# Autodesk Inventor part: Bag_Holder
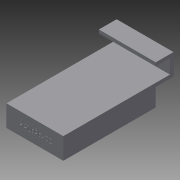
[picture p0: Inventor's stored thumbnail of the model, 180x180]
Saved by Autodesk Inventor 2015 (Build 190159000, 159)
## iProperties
Created: 2017-04
Part Number: Bag_Holder
Material: Generisch
Document SubType Name: Modeling
Designer: Andreas
Density: 1 g/cm^3
Appearance: Vorgabe
Author: Andreas
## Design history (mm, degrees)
sketch "Skizze1"
  geometry: L1 (0, 0)-(80, 0); L2 (80, 0)-(80, 130); L3 (80, 130)-(0, 130); L4 (0, 130)-(0, 0)
  constraints: 8 end point, 2 perpendicular, 1 horizontal
  dimensions: "d0" = 80 distance of L1.start L1.end; "d1" = 130 distance of L1.end L2.end; "d2" = 80 distance of L2.end L3.end
extrude "Extrusion1" new body sketch "Skizze1" distance "d3" = 30; taper "d4" = 0 deg
sketch "Skizze2"
  geometry: L1 (80, 0)-(0, 0) reference; L2 (0, 0)-(0, -30) reference; L3 (80, -30)-(0, -30) reference; L4 (80, 0)-(80, -30) reference; L5 (5, -25)-(5, -5); L6 (5, -5)-(75, -5); L7 (75, -5)-(75, -25); L8 (75, -25)-(5, -25); 1 further point
  constraints: 8 end point, 3 other
  dimensions: "d5" = 5 distance between parallel lines of L2 L5; "d77" = 20 distance of L5.start L5.end (derived); "d78" = 70 distance of L5.end L6.end (derived)
extrude "Extrusion2" cut sketch "Skizze2" distance "d6" = 125; taper "d7" = 0 deg
sketch "Skizze7"
  geometry: L1 (-59.744, 88.491)-(-60.39, 85.615); L2 (-62.939, 74.608)-(-63.588, 71.717); L3 (-52.046, 75.49)-(-55.468, 75.49); L4 (-55.468, 75.49)-(-53.397, 84.729); L5 (-53.397, 84.729)-(-49.199, 84.729); L6 (-49.199, 84.729)-(-46.708, 79.416); L7 (-46.708, 79.416)-(-45.517, 84.729); L8 (-45.517, 84.729)-(-42.09, 84.729); L9 (-42.09, 84.729)-(-44.161, 75.49); L10 (-44.161, 75.49)-(-47.759, 75.49); L11 (-47.759, 75.49)-(-50.681, 81.559); L12 (-50.681, 81.559)-(-52.046, 75.49); L13 (-37.885, 82.34)-(-39.422, 75.49); L14 (-39.422, 75.49)-(-43.008, 75.49); L15 (-43.008, 75.49)-(-40.934, 84.729); L16 (-40.934, 84.729)-(-36.491, 84.729); L17 (-33.974, 78.445)-(-32.628, 76.694); L18 (-32.628, 76.694)-(-29.431, 81.214); L19 (-28.102, 83.093)-(-29.431, 81.214); L20 (-25.841, 84.696)-(-19.531, 84.696); L21 (-19.531, 84.696)-(-21.589, 75.536); L22 (-21.589, 75.536)-(-25.189, 75.536); L23 (-25.189, 75.536)-(-24.796, 77.116); L24 (-24.796, 77.116)-(-28.601, 77.154); L25 (-28.601, 77.154)-(-29.664, 75.536); L26 (-29.664, 75.536)-(-33.863, 75.536); L27 (-37.885, 82.34)-(-36.33, 82.34); L28 (-35.294, 82.34)-(-36.33, 82.34); L29 (-38.01, 80.264)-(-34.918, 80.264); L30 (-23.795, 82.34)-(-24.409, 79.416); L31 (-24.409, 79.416)-(-27.115, 79.416); L32 (-27.115, 79.416)-(-25.739, 81.512); L33 (-18.394, 84.695)-(-20.442, 75.489); L34 (-20.442, 75.489)-(-14.707, 75.489); L35 (-18.394, 84.695)-(-13.718, 84.695); L36 (-14.707, 75.489)-(-12.399, 75.514); L37 (-10.901, 84.695)-(-13.718, 84.695); L38 (-12.846, 82.34)-(-15.353, 82.34); L39 (-15.353, 82.34)-(-16.359, 77.863); L40 (-16.359, 77.863)-(-13.579, 77.863); 115 further points
  constraints: 80 end point, 9 parallel, 8 horizontal, 7 point on line, 1 collinear, 132 other
extrude "Extrusion7" cut sketch "Skizze7" distance "d72" = 3; taper "d73" = 0 deg
sketch "Skizze8"
  geometry: L1 (63.78, 11.593)-(16.426, 11.593); L2 (16.426, 11.593)-(16.426, 20.574); L3 (16.426, 20.574)-(63.78, 20.574); L4 (63.78, 20.574)-(63.78, 11.593); 1 further point
  constraints: 2 other
extrude "Extrusion8" cut sketch "Skizze8" distance "d74" = 3; taper "d75" = 0 deg
sketch "Skizze9"
  geometry: L1 (0, -30)-(80, -30); L2 (80, -30)-(80, -25); L3 (80, -25)-(0, -25); L4 (0, -25)-(0, -30); 1 further point
  constraints: 8 end point, 2 parallel, 1 horizontal, 1 perpendicular
extrude "Extrusion9" join sketch "Skizze9" distance "d80" = 25; taper "d81" = 0 deg
sketch "Skizze10"
  geometry: L1 (0, 155)-(-25, 155); L2 (-25, 155)-(-25, 130); L3 (-25, 130)-(-20, 130); L4 (-20, 130)-(-20, 150); L5 (-20, 150)-(0, 150); L6 (0, 0)-(0, 155) reference; 1 further point
  constraints: 10 end point, 4 perpendicular, 1 horizontal, 1 point on line
  dimensions: "d84" = 25 distance of L1.start L1.end; "d85" = 25 distance of L1.end L2.end; "d86" = 5 distance of L2.end L3.end; "d87" = 20 distance of L3.end L4.end
extrude "Extrusion11" join sketch "Skizze10" distance "d88" = 80; taper "d89" = 0 deg
node "Volumenkörper1"
node "Projizierte Kontur1"
